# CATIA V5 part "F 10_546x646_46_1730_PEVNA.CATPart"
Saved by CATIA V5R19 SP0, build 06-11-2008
Definition: F 10_546x646_46_1730_PEVNA
Nomenclature: F 10_546x646_46_1730_PEVNA
Description: PART--DESC
Material "Steel": density 7860 kg/m3, Young's modulus 2e+11 Pa, Poisson ratio 0.266, thermal expansion 1.17e-05 1/K
Bounding box of the stored display mesh (mm): x -323 to 323, y -298 to 298, z 96 to 142
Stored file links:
  G:\UTB\Kombinované\Bakalářská práce\Catia\FORMA\F 10_546x646_46_1730_PEVNA.CATPart
  D:\Aplikace\CATIA\Nová složka\win_b64\startup\materials\Catalog.CATMaterial
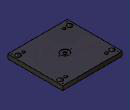
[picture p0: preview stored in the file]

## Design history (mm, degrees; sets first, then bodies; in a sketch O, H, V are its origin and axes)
Body1 "F 10_546646_46_1730" (main body)
  Solid1: solid without history
  Sketch1 on face of Solid1, origin (0, 0, 142), H (1, 0, 0), V (0, 1, 0)
    point P1 (0, 0)
    construction line L1 (300, 275) -> (300, -275)
    construction line L2 (300, -275) -> (-300, -275)
    construction line L3 (-300, -275) -> (-300, 275)
    construction line L4 (-300, 275) -> (300, 275)
    point P4 (-300, -275)
    reference intersected line E1 through (0, 0) direction (0, 1) from yz-plane
    reference intersected line E2 through (0, 0) direction (-1, 0) from zx-plane
    distance L4 L2 = 550
    distance L1 L3 = 600
    vertical: L1 V, L3 V
    horizontal: L2 H, L4 H
    equidistance: L1 L3 P1, L2 L4 P1
    coincidence: P1 E1, P1 E2
  Sketch2 on face of Solid1, origin (-300, -275, 142), H (1, 0, 0), V (0, 1, 0)
    point P1 (0, 0)
    reference projected point E1 (0, 0) from Sketch1.P4
    coincidence: E1 P1
  Hole1: placed by Sketch2, at (-300, -275, 142) direction (0, 0, -1), diameter 6.647, depth 12, V-bottom angle 120, countersink depth 0.5, countersink angle 90, threaded "M8", thread diameter 8, thread depth 10, pitch 1.25
  UserPattern1: of Hole1, copies 4, at the points of Sketch1
  Sketch3 on face of Solid1, origin (0, 0, 142), H (1, 0, 0), V (0, 1, 0)
    point P1 (64, 0)
    reference intersected line E1 through (0, 0) direction (-1, 0) from zx-plane
    reference intersected line E2 through (0, 0) direction (0, 1) from yz-plane
    reference intersected line E3 through (0, 0) direction (0, 1) from yz-plane
    point P4 (-64, 0)
    distance P1 E2 = 64
    coincidence: P1 E1
    symmetry: P1 P4 E3
  Sketch4 on face of Solid1, origin (-64, 0, 142), H (1, 0, 0), V (0, 1, 0)
    point P1 (0, 0)
    reference projected point E1 (0, 0) from Sketch3.P4
    coincidence: E1 P1
  Hole2: placed by Sketch4, at (-64, 0, 142) direction (0, 0, -1), diameter 4.134, depth 14, V-bottom angle 120, countersink depth 0.5, countersink angle 90, threaded "M5", thread diameter 5, thread depth 12, pitch 0.8
  UserPattern2: of Hole2, copies 2, at the points of Sketch3
  Sketch5 on face of Solid1, origin (20.7082, 35.6085, 96), H (1, 0, 0), V (0, -1, 0)
    point P1 (-20.7082, 35.6085)
    reference intersected line E1 through (0, 35.6085) direction (1, 0) from zx-plane
    reference intersected line E2 through (-20.7082, 0) direction (0, 1) from yz-plane
    coincidence: P1 E1, P1 E2
  Hole3: placed by Sketch5, at (0, 0, 96) direction (0, 0, 1), diameter 50, depth 38
  Sketch6 on face of Solid1, origin (0, 0, 138), H (1, 0, 0), V (0, 1, 0)
    point P1 (0, 0)
    reference intersected line E1 through (0, 0) direction (-1, 0) from zx-plane
    reference intersected line E2 through (0, 0) direction (0, 1) from yz-plane
    coincidence: P1 E1, P1 E2
  Hole4: placed by Sketch6, at (0, 0, 138) direction (0, 0, -1), diameter 30.05, through (limit type 3), countersink depth 2, countersink angle 90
